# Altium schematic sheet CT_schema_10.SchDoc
size 146 x 119 mm
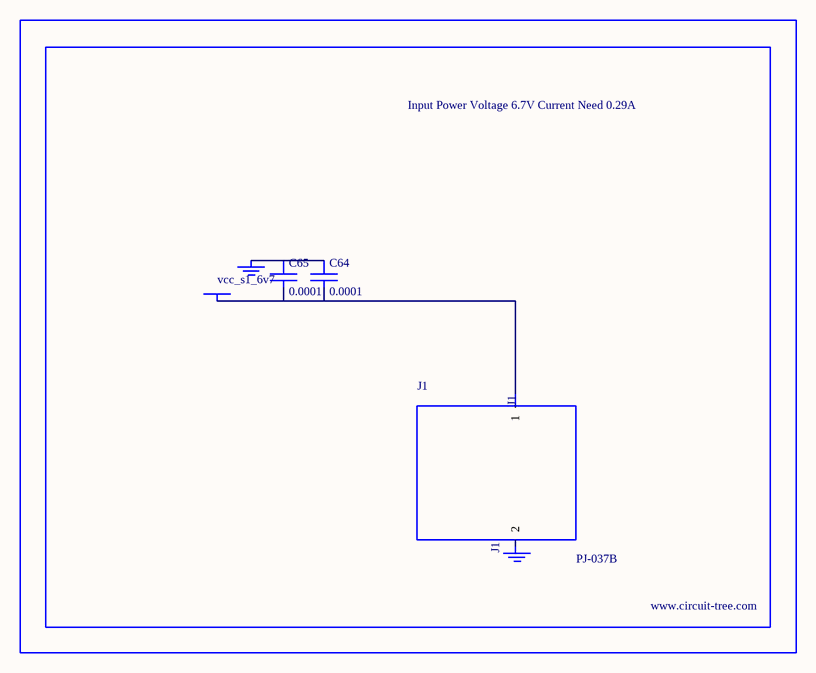
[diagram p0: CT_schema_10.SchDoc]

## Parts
BORDER9  (no value)
C64  0.0001  [EXV-9H]
C65  0.0001  [EXV-9H]
GND_INSTANCE_9_0  (no value)
GND_INSTANCE_9_1  (no value)
J1  PJ-037B  [PJ-037B_PACKAGE]
POWER_INSTANCE_9_0  vcc_s1_6v7

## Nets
NetC64_1: C64.1 C65.1 GND_INSTANCE_9_0.0(GND)
NetC64_2: C64.2 C65.2 J1.1 POWER_INSTANCE_9_0.0(PWR)

Not connected (* = marked no-connect by the designer): GND_INSTANCE_9_1 0(GND); J1 2

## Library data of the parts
BORDER9 = BORDER_PAGE9
C64 C65 = EDK107M035A9HAA
GND_INSTANCE_9_0 GND_INSTANCE_9_1 = GND
POWER_INSTANCE_9_0 = PWR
